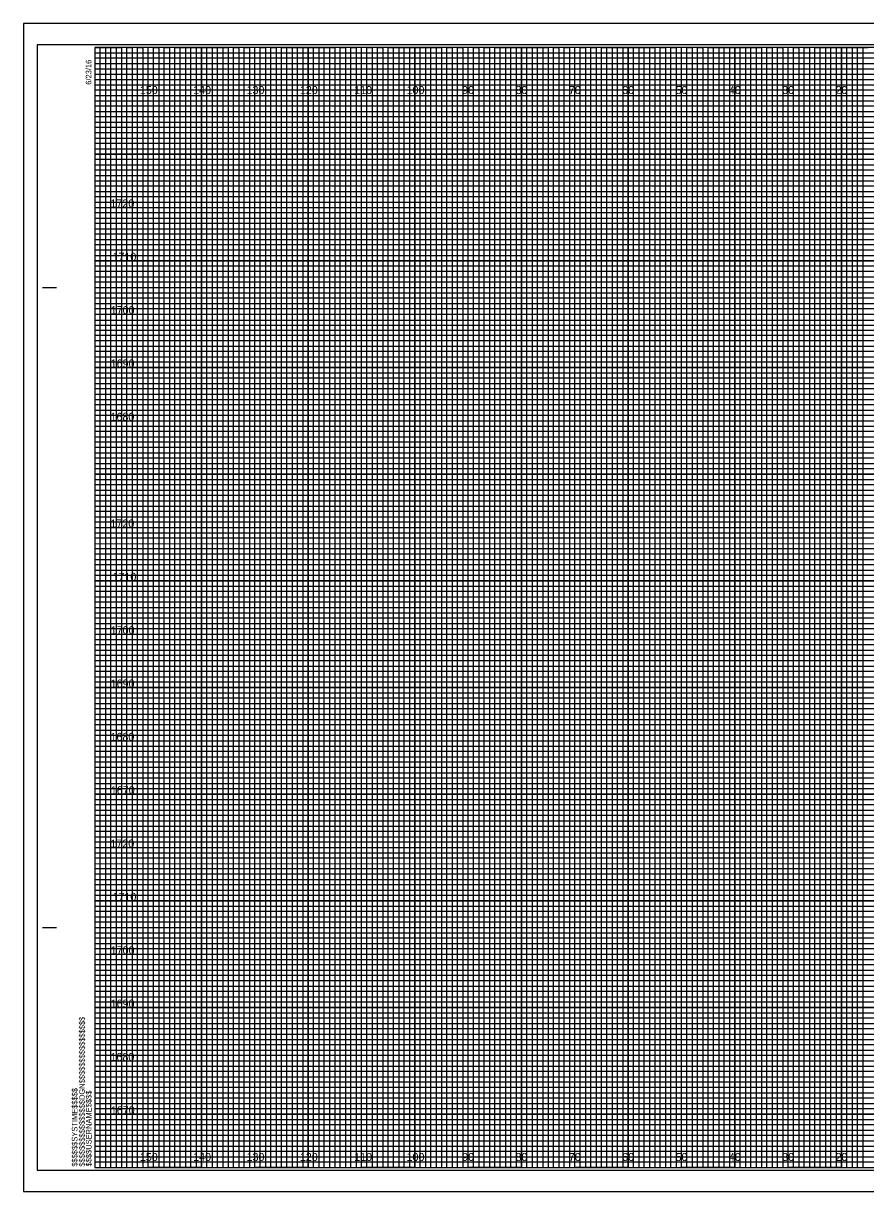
# Model space of a CAD drawing. Extents: x 656 to 993, y -2 to 2857.
# Drawn here: x 656.3 to 814.2, y 2198.3 to 2417.3 of the extents above; entities that cross this region are included whole.
import ezdxf

# ---------------------------------------------------------------- set-up
doc = ezdxf.new("R2010")
doc.units = 0
for name, color, linetype in [('Prop RDY Alternate Text Blue', 7, 'Continuous'), ('Prop Retaining Wall', 7, 'Continuous'), ('Prop SS Cut Line', 7, 'Continuous'), ('Prop SS Fill Line', 7, 'Continuous'), ('Prop SS Transition Line', 7, 'Continuous'), ('Raster_Level_0', 7, 'Continuous'), ('Raster_Level_3', 7, 'Continuous'), ('Scratch_Level_3', 7, 'Continuous'), ('Scratch_Level_7', 7, 'Continuous'), ('Typical Guardrail CELL', 7, 'Continuous'), ('Typical Text Asphalt at Bridge Approach CELL', 7, 'Continuous')]:
    doc.layers.add(name, color=color, linetype=linetype)

msp = doc.modelspace()

# ---------------------------------------------------------------- linework, layer by layer
at = {"layer": 'Prop RDY Alternate Text Blue'}
for p, q in [((679.74, 2202.8), (679.74, 2412.8)), ((689.74, 2202.8), (689.74, 2412.8)), ((699.74, 2202.8), (699.74, 2412.8)), ((709.74, 2202.8), (709.74, 2412.8)), ((719.74, 2202.8), (719.74, 2412.8)), ((729.74, 2202.8), (729.74, 2412.8)), ((739.74, 2202.8), (739.74, 2412.8)), ((749.74, 2202.8), (749.74, 2412.8)), ((759.74, 2202.8), (759.74, 2412.8)), ((769.74, 2202.8), (769.74, 2412.8)), ((779.74, 2202.8), (779.74, 2412.8)), ((789.74, 2202.8), (789.74, 2412.8)), ((799.74, 2202.8), (799.74, 2412.8)), ((809.74, 2202.8), (809.74, 2412.8)), ((669.74, 2402.8), (989.74, 2402.8)), ((669.74, 2392.8), (989.74, 2392.8)), ((669.74, 2382.8), (989.74, 2382.8)), ((669.74, 2372.8), (989.74, 2372.8)), ((669.74, 2362.8), (989.74, 2362.8)), ((669.74, 2352.8), (989.74, 2352.8)), ((669.74, 2342.8), (989.74, 2342.8)), ((669.74, 2332.8), (989.74, 2332.8)), ((669.74, 2322.8), (989.74, 2322.8)), ((669.74, 2312.8), (989.74, 2312.8)), ((669.74, 2302.8), (989.74, 2302.8)), ((669.74, 2292.8), (989.74, 2292.8)), ((669.74, 2282.8), (989.74, 2282.8)), ((669.74, 2272.8), (989.74, 2272.8)), ((669.74, 2262.8), (989.74, 2262.8)), ((669.74, 2252.8), (989.74, 2252.8)), ((669.74, 2242.8), (989.74, 2242.8)), ((669.74, 2232.8), (989.74, 2232.8)), ((669.74, 2222.8), (989.74, 2222.8)), ((669.74, 2212.8), (989.74, 2212.8))]:
    msp.add_line(p, q, dxfattribs=at)
at = {"layer": 'Prop Retaining Wall'}
for p, q in [((659.94, 2367.8), (662.44, 2367.8)), ((660.04, 2367.8), (662.54, 2367.8)), ((659.94, 2247.8), (662.44, 2247.8)), ((660.04, 2247.8), (662.54, 2247.8)), ((669.74, 2202.8), (669.74, 2202.8)), ((669.74, 2202.8), (669.74, 2202.8)), ((669.74, 2202.8), (669.74, 2202.8)), ((669.74, 2202.8), (669.74, 2202.8)), ((669.74, 2202.8), (669.74, 2202.8)), ((669.74, 2202.8), (669.74, 2202.8)), ((669.74, 2202.8), (669.74, 2202.8))]:
    msp.add_line(p, q, dxfattribs=at)
msp.add_lwpolyline([(989.74, 2412.8), (669.74, 2412.8), (669.74, 2202.8), (989.74, 2202.8)], close=True, dxfattribs=at)
at = {"layer": 'Prop SS Cut Line'}
for points in [[(669.74, 2412.8), (674.74, 2412.8), (674.74, 2202.8), (684.74, 2202.8), (684.74, 2412.8), (694.74, 2412.8), (694.74, 2202.8), (704.74, 2202.8), (704.74, 2412.8), (714.74, 2412.8), (714.74, 2202.8), (724.74, 2202.8), (724.74, 2412.8), (734.74, 2412.8), (734.74, 2202.8), (744.74, 2202.8), (744.74, 2412.8), (754.74, 2412.8), (754.74, 2202.8), (764.74, 2202.8), (764.74, 2412.8), (774.74, 2412.8), (774.74, 2202.8), (784.74, 2202.8), (784.74, 2412.8), (794.74, 2412.8), (794.74, 2202.8), (804.74, 2202.8), (804.74, 2412.8), (814.74, 2412.8)], [(669.74, 2407.8), (944.74, 2407.8)], [(669.74, 2387.8), (989.74, 2387.8), (989.74, 2397.8), (669.74, 2397.8)], [(669.74, 2367.8), (989.74, 2367.8), (989.74, 2377.8), (669.74, 2377.8)], [(669.74, 2347.8), (989.74, 2347.8), (989.74, 2357.8), (669.74, 2357.8)], [(669.74, 2327.8), (989.74, 2327.8), (989.74, 2337.8), (669.74, 2337.8)], [(669.74, 2307.8), (989.74, 2307.8), (989.74, 2317.8), (669.74, 2317.8)], [(669.74, 2287.8), (989.74, 2287.8), (989.74, 2297.8), (669.74, 2297.8)], [(669.74, 2267.8), (989.74, 2267.8), (989.74, 2277.8), (669.74, 2277.8)], [(669.74, 2247.8), (989.74, 2247.8), (989.74, 2257.8), (669.74, 2257.8)], [(669.74, 2227.8), (989.74, 2227.8), (989.74, 2237.8), (669.74, 2237.8)], [(669.74, 2207.8), (989.74, 2207.8), (989.74, 2217.8), (669.74, 2217.8)]]:
    msp.add_lwpolyline(points, dxfattribs=at)
at = {"layer": 'Prop SS Fill Line'}
for p, q in [((679.74, 2412.8), (669.74, 2412.8)), ((679.74, 2202.8), (679.74, 2412.8)), ((699.74, 2412.8), (689.74, 2412.8)), ((689.74, 2412.8), (689.74, 2202.8)), ((699.74, 2202.8), (699.74, 2412.8)), ((719.74, 2412.8), (709.74, 2412.8)), ((709.74, 2412.8), (709.74, 2202.8)), ((719.74, 2202.8), (719.74, 2412.8)), ((739.74, 2412.8), (729.74, 2412.8)), ((729.74, 2412.8), (729.74, 2202.8)), ((739.74, 2202.8), (739.74, 2412.8)), ((759.74, 2412.8), (749.74, 2412.8)), ((749.74, 2412.8), (749.74, 2202.8)), ((759.74, 2202.8), (759.74, 2412.8)), ((779.74, 2412.8), (769.74, 2412.8)), ((769.74, 2412.8), (769.74, 2202.8)), ((779.74, 2202.8), (779.74, 2412.8)), ((799.74, 2412.8), (789.74, 2412.8)), ((789.74, 2412.8), (789.74, 2202.8)), ((799.74, 2202.8), (799.74, 2412.8)), ((819.74, 2412.8), (809.74, 2412.8)), ((809.74, 2412.8), (809.74, 2202.8)), ((689.74, 2202.8), (679.74, 2202.8)), ((709.74, 2202.8), (699.74, 2202.8)), ((729.74, 2202.8), (719.74, 2202.8)), ((749.74, 2202.8), (739.74, 2202.8)), ((769.74, 2202.8), (759.74, 2202.8)), ((789.74, 2202.8), (779.74, 2202.8)), ((809.74, 2202.8), (799.74, 2202.8))]:
    msp.add_line(p, q, dxfattribs=at)
for points in [[(669.74, 2402.8), (989.74, 2402.8), (989.74, 2392.8), (669.74, 2392.8)], [(669.74, 2382.8), (989.74, 2382.8), (989.74, 2372.8), (669.74, 2372.8)], [(669.74, 2362.8), (989.74, 2362.8), (989.74, 2352.8), (669.74, 2352.8)], [(669.74, 2342.8), (989.74, 2342.8), (989.74, 2332.8), (669.74, 2332.8)], [(669.74, 2322.8), (989.74, 2322.8), (989.74, 2312.8), (669.74, 2312.8)], [(669.74, 2302.8), (989.74, 2302.8), (989.74, 2292.8), (669.74, 2292.8)], [(669.74, 2282.8), (989.74, 2282.8), (989.74, 2272.8), (669.74, 2272.8)], [(669.74, 2262.8), (989.74, 2262.8), (989.74, 2252.8), (669.74, 2252.8)], [(669.74, 2242.8), (989.74, 2242.8), (989.74, 2232.8), (669.74, 2232.8)], [(669.74, 2222.8), (989.74, 2222.8), (989.74, 2212.8), (669.74, 2212.8)]]:
    msp.add_lwpolyline(points, dxfattribs=at)
at = {"layer": 'Prop SS Transition Line'}
for p, q in [((669.74, 2411.8), (929.74, 2411.8)), ((929.74, 2410.78), (669.74, 2410.78)), ((669.74, 2410.78), (669.74, 2409.8)), ((669.74, 2409.8), (929.74, 2409.8)), ((929.74, 2408.69), (669.74, 2408.69)), ((669.74, 2408.69), (669.74, 2406.8)), ((669.74, 2406.8), (989.74, 2406.8))]:
    msp.add_line(p, q, dxfattribs=at)
for points in [[(669.74, 2405.8), (939.74, 2405.8), (989.74, 2405.8), (989.74, 2404.8), (669.74, 2404.8)], [(669.74, 2403.8), (989.74, 2403.8), (989.74, 2401.8), (669.74, 2401.8)], [(669.74, 2400.8), (989.74, 2400.8), (989.74, 2399.8), (669.74, 2399.78)], [(669.74, 2398.8), (989.74, 2398.8), (989.74, 2396.8), (669.74, 2396.8)], [(669.74, 2395.8), (989.74, 2395.8), (989.74, 2394.8), (669.74, 2394.8)], [(669.74, 2393.8), (989.74, 2393.8), (989.74, 2391.8), (669.74, 2391.8)], [(669.74, 2390.8), (989.74, 2390.8), (989.74, 2389.8), (669.74, 2389.8)], [(669.74, 2388.8), (989.74, 2388.8), (989.74, 2386.8), (669.74, 2386.8)], [(669.74, 2385.8), (989.74, 2385.8), (989.74, 2384.8), (669.74, 2384.8)], [(669.74, 2383.8), (989.74, 2383.8), (989.74, 2381.8), (669.74, 2381.8)], [(669.74, 2380.8), (989.74, 2380.8), (989.74, 2379.8), (669.74, 2379.8)], [(669.74, 2378.8), (989.74, 2378.8), (989.74, 2376.75), (989.74, 2375.8), (989.74, 2374.8), (669.74, 2374.8)], [(669.74, 2376.8), (989.74, 2376.8), (989.74, 2375.8), (669.74, 2375.8)], [(669.74, 2373.8), (989.74, 2373.8), (989.74, 2371.8), (669.74, 2371.83)], [(669.74, 2371.83), (989.74, 2371.8), (989.74, 2370.8), (669.74, 2370.8)], [(669.74, 2369.8), (989.74, 2369.8), (989.74, 2368.8), (669.74, 2368.8)], [(669.74, 2366.8), (989.74, 2366.8), (989.74, 2365.8), (669.74, 2365.8)], [(669.74, 2364.8), (989.74, 2364.8), (989.74, 2363.8), (669.74, 2363.8)], [(669.67, 2361.69), (989.74, 2361.69), (989.74, 2360.68), (669.67, 2360.68)], [(669.74, 2359.8), (989.74, 2359.8), (989.74, 2358.8), (669.74, 2358.8)], [(669.74, 2356.8), (989.74, 2356.8), (989.74, 2355.8), (669.74, 2355.8)], [(669.74, 2354.8), (989.74, 2354.8), (989.74, 2353.8), (669.74, 2353.8)], [(669.74, 2351.8), (989.74, 2351.8), (989.74, 2350.8), (669.74, 2350.8)], [(669.74, 2349.8), (989.74, 2349.8), (989.74, 2348.8), (669.74, 2348.8)], [(669.74, 2346.8), (989.74, 2346.8), (989.74, 2345.8), (669.74, 2345.8)], [(669.74, 2344.8), (989.74, 2344.8), (989.74, 2343.8), (669.74, 2343.8)], [(669.74, 2341.8), (989.74, 2341.8), (989.73, 2340.78), (669.74, 2340.8)], [(669.74, 2339.8), (989.74, 2339.8), (989.74, 2338.8), (669.74, 2338.8)], [(669.74, 2336.8), (989.74, 2336.8), (989.74, 2335.8), (669.74, 2335.8)], [(669.74, 2334.8), (989.74, 2334.8), (989.74, 2333.8), (669.74, 2333.8)], [(669.74, 2331.8), (989.74, 2331.8), (989.74, 2330.8), (669.74, 2330.8)], [(669.74, 2329.8), (989.74, 2329.8), (989.74, 2328.8), (669.74, 2328.8)], [(669.74, 2326.8), (989.74, 2326.8), (989.74, 2325.8), (669.74, 2325.8)], [(669.74, 2324.8), (989.74, 2324.8), (989.74, 2323.8), (669.74, 2323.8)], [(669.74, 2321.8), (989.74, 2321.8), (989.74, 2320.8), (669.74, 2320.8)], [(669.74, 2319.79), (989.81, 2319.71), (989.74, 2318.8), (669.74, 2318.8)], [(669.74, 2316.8), (989.74, 2316.8), (989.74, 2315.8), (669.74, 2315.8)], [(669.74, 2314.8), (989.74, 2314.8), (989.74, 2313.8), (669.74, 2313.8)], [(669.74, 2311.8), (989.74, 2311.8), (989.74, 2310.8), (669.74, 2310.8)], [(669.74, 2309.8), (989.74, 2309.8), (989.74, 2308.8), (669.74, 2308.8)], [(669.74, 2306.8), (989.74, 2306.8), (989.74, 2305.8), (669.74, 2305.8)], [(669.74, 2304.8), (989.74, 2304.8), (989.74, 2303.8), (669.74, 2303.8)], [(669.74, 2301.8), (989.74, 2301.8), (989.74, 2300.8), (669.74, 2300.8)], [(669.74, 2299.8), (989.74, 2299.8), (989.74, 2298.8), (669.74, 2298.8)], [(669.74, 2296.8), (989.74, 2296.8), (989.74, 2295.8), (669.74, 2295.8)], [(669.74, 2294.8), (989.74, 2294.8), (989.74, 2293.8), (669.74, 2293.8)], [(669.74, 2291.8), (989.74, 2291.8), (989.74, 2290.8), (669.74, 2290.8)], [(669.74, 2289.8), (989.74, 2289.8), (989.74, 2288.8), (669.74, 2288.8)], [(669.74, 2286.8), (989.74, 2286.8), (989.74, 2285.8), (669.74, 2285.8)], [(669.74, 2284.8), (989.74, 2284.8), (989.74, 2283.8), (669.74, 2283.8)], [(669.74, 2281.8), (989.74, 2281.8), (989.73, 2280.78), (669.74, 2280.8)], [(669.74, 2279.8), (989.74, 2279.8), (989.74, 2278.8), (669.74, 2278.8)], [(669.74, 2276.8), (989.74, 2276.8), (989.74, 2275.8), (669.74, 2275.8)], [(669.74, 2274.8), (989.74, 2274.8), (989.74, 2273.8), (669.74, 2273.8)], [(669.74, 2271.8), (989.74, 2271.8), (989.74, 2270.8), (669.74, 2270.8)], [(669.74, 2269.8), (989.74, 2269.8), (989.74, 2268.8), (669.74, 2268.8)], [(669.74, 2266.8), (989.74, 2266.8), (989.74, 2265.8), (669.74, 2265.8)], [(669.74, 2264.8), (989.74, 2264.8), (989.74, 2263.8), (669.74, 2263.8)], [(669.74, 2261.8), (989.74, 2261.8), (989.74, 2260.8), (669.74, 2260.8)], [(669.74, 2259.79), (989.81, 2259.71), (989.74, 2258.8), (669.74, 2258.8)], [(669.74, 2256.8), (989.74, 2256.8), (989.74, 2255.8), (669.74, 2255.8)], [(669.74, 2254.8), (989.74, 2254.8), (989.74, 2253.8), (669.74, 2253.8)], [(669.74, 2251.8), (989.74, 2251.8), (989.74, 2250.8), (669.74, 2250.8)], [(669.74, 2249.8), (989.74, 2249.8), (989.74, 2248.8), (669.74, 2248.8)], [(669.74, 2246.8), (989.74, 2246.8), (989.74, 2245.8), (669.74, 2245.8)], [(669.74, 2244.8), (989.74, 2244.8), (989.74, 2243.8), (669.74, 2243.8)], [(669.74, 2241.8), (989.74, 2241.8), (989.74, 2240.8), (669.74, 2240.8)], [(669.74, 2239.8), (989.74, 2239.8), (989.74, 2238.8), (669.74, 2238.8)], [(669.74, 2236.8), (989.74, 2236.8), (989.74, 2235.8), (669.74, 2235.8)], [(669.74, 2234.8), (989.74, 2234.8), (989.74, 2233.8), (669.74, 2233.8)], [(669.74, 2231.8), (989.74, 2231.8), (989.74, 2230.8), (669.74, 2230.8)], [(669.74, 2229.8), (989.74, 2229.8), (989.74, 2228.8), (669.74, 2228.8)], [(669.74, 2226.8), (989.74, 2226.8), (989.74, 2225.8), (669.74, 2225.8)], [(669.74, 2224.8), (989.74, 2224.8), (989.74, 2223.8), (669.74, 2223.8)], [(669.74, 2221.8), (989.74, 2221.8), (989.74, 2220.8), (669.74, 2220.8)], [(669.74, 2219.8), (989.74, 2219.8), (989.74, 2218.8), (669.74, 2218.8)], [(669.74, 2216.8), (989.74, 2216.8), (989.74, 2215.8), (669.74, 2215.8)], [(669.74, 2214.8), (989.74, 2214.8), (989.74, 2213.8), (669.74, 2213.8)], [(669.74, 2211.8), (989.74, 2211.8), (989.74, 2210.8), (669.74, 2210.8)], [(669.74, 2209.8), (989.74, 2209.8), (989.74, 2208.8), (669.74, 2208.8)], [(669.74, 2206.8), (989.74, 2206.8), (989.74, 2205.8), (669.74, 2205.8)], [(669.74, 2204.8), (989.74, 2204.8), (989.74, 2203.8), (669.74, 2203.8)]]:
    msp.add_lwpolyline(points, dxfattribs=at)
at = {"layer": 'Raster_Level_3'}
for points in [[(669.74, 2202.8), (670.74, 2202.8), (670.74, 2412.8), (671.74, 2412.8), (671.74, 2202.8)], [(671.74, 2202.8), (672.74, 2202.8), (672.74, 2412.8), (673.74, 2412.8), (673.74, 2202.8)], [(674.74, 2202.8), (675.74, 2202.8), (675.74, 2412.8), (676.74, 2412.8), (676.74, 2202.8)], [(676.74, 2202.8), (677.74, 2202.8), (677.74, 2412.8), (678.74, 2412.8), (678.74, 2202.8)], [(679.74, 2202.8), (680.74, 2202.8), (680.74, 2412.8), (681.74, 2412.8), (681.74, 2202.8)], [(681.74, 2202.8), (682.74, 2202.8), (682.74, 2412.8), (683.74, 2412.8), (683.74, 2202.8)], [(684.74, 2202.8), (685.74, 2202.8), (685.74, 2412.8), (686.74, 2412.8), (686.74, 2202.8)], [(686.74, 2202.8), (687.74, 2202.8), (687.74, 2412.8), (688.74, 2412.8), (688.74, 2202.8)], [(689.74, 2202.8), (690.74, 2202.8), (690.74, 2412.8), (691.74, 2412.8), (691.74, 2202.8)], [(691.74, 2202.8), (692.74, 2202.8), (692.74, 2412.8), (693.74, 2412.8), (693.74, 2202.8)], [(694.74, 2202.8), (695.74, 2202.8), (695.74, 2412.8), (696.74, 2412.8), (696.74, 2202.8)], [(696.74, 2202.8), (697.74, 2202.8), (697.74, 2412.8), (698.74, 2412.8), (698.74, 2202.8)], [(699.74, 2202.8), (700.74, 2202.8), (700.74, 2412.8), (701.74, 2412.8), (701.74, 2202.8)], [(701.74, 2202.8), (702.74, 2202.8), (702.74, 2412.8), (703.74, 2412.8), (703.74, 2202.8)], [(704.74, 2202.8), (705.74, 2202.8), (705.74, 2412.8), (706.74, 2412.8), (706.74, 2202.8)], [(706.74, 2202.8), (707.74, 2202.8), (707.74, 2412.8), (708.74, 2412.8), (708.74, 2202.8)], [(709.74, 2202.8), (710.74, 2202.8), (710.74, 2412.8), (711.74, 2412.8), (711.74, 2202.8)], [(711.74, 2202.8), (712.74, 2202.8), (712.74, 2412.8), (713.74, 2412.8), (713.74, 2202.8)], [(714.74, 2202.8), (715.74, 2202.8), (715.74, 2412.8), (716.74, 2412.8), (716.74, 2202.8)], [(716.74, 2202.8), (717.74, 2202.8), (717.74, 2412.8), (718.74, 2412.8), (718.74, 2202.8)], [(719.74, 2202.8), (720.74, 2202.8), (720.74, 2412.8), (721.74, 2412.8), (721.74, 2202.8)], [(721.74, 2202.8), (722.74, 2202.8), (722.74, 2412.8), (723.74, 2412.8), (723.74, 2202.8)], [(724.74, 2202.8), (725.74, 2202.8), (725.74, 2412.8), (726.74, 2412.8), (726.74, 2202.8)], [(726.74, 2202.8), (727.74, 2202.8), (727.74, 2412.8), (728.74, 2412.8), (728.74, 2202.8)], [(729.74, 2202.8), (730.74, 2202.8), (730.74, 2412.8), (731.74, 2412.8), (731.74, 2202.8)], [(731.74, 2202.8), (732.74, 2202.8), (732.74, 2412.8), (733.74, 2412.8), (733.74, 2202.8)], [(734.74, 2202.8), (735.74, 2202.8), (735.74, 2412.8), (736.74, 2412.8), (736.74, 2202.8)], [(736.74, 2202.8), (737.74, 2202.8), (737.74, 2412.8), (738.74, 2412.8), (738.74, 2202.8)], [(739.74, 2202.8), (740.74, 2202.8), (740.74, 2412.8), (741.74, 2412.8), (741.74, 2202.8)], [(741.74, 2202.8), (742.74, 2202.8), (742.74, 2412.8), (743.74, 2412.8), (743.74, 2202.8)], [(744.74, 2202.8), (745.74, 2202.8), (745.74, 2412.8), (746.74, 2412.8), (746.74, 2202.8)], [(746.74, 2202.8), (747.74, 2202.8), (747.74, 2412.8), (748.74, 2412.8), (748.74, 2202.8)], [(749.74, 2202.8), (750.74, 2202.8), (750.74, 2412.8), (751.74, 2412.8), (751.74, 2202.8)], [(751.74, 2202.8), (752.74, 2202.8), (752.74, 2412.8), (753.74, 2412.8), (753.74, 2202.8)], [(754.74, 2202.8), (755.74, 2202.8), (755.74, 2412.8), (756.74, 2412.8), (756.74, 2202.8)], [(756.74, 2202.8), (757.74, 2202.8), (757.74, 2412.8), (758.74, 2412.8), (758.74, 2202.8)], [(759.74, 2202.8), (760.74, 2202.8), (760.74, 2412.8), (761.74, 2412.8), (761.74, 2202.8)], [(761.74, 2202.8), (762.74, 2202.8), (762.74, 2412.8), (763.74, 2412.8), (763.74, 2202.8)], [(764.74, 2202.8), (765.74, 2202.8), (765.74, 2412.8), (766.74, 2412.8), (766.74, 2202.8)], [(766.74, 2202.8), (767.74, 2202.8), (767.74, 2412.8), (768.74, 2412.8), (768.74, 2202.8)], [(769.74, 2202.8), (770.74, 2202.8), (770.74, 2412.8), (771.74, 2412.8), (771.74, 2202.8)], [(771.74, 2202.8), (772.74, 2202.8), (772.74, 2412.8), (773.74, 2412.8), (773.74, 2202.8)], [(774.74, 2202.8), (775.74, 2202.8), (775.74, 2412.8), (776.74, 2412.8), (776.74, 2202.8)], [(776.74, 2202.8), (777.74, 2202.8), (777.74, 2412.8), (778.74, 2412.8), (778.74, 2202.8)], [(779.74, 2202.8), (780.74, 2202.8), (780.74, 2412.8), (781.74, 2412.8), (781.74, 2202.8)], [(781.74, 2202.8), (782.74, 2202.8), (782.74, 2412.8), (783.74, 2412.8), (783.74, 2202.8)], [(784.74, 2202.8), (785.74, 2202.8), (785.74, 2412.8), (786.74, 2412.8), (786.74, 2202.8)], [(786.74, 2202.8), (787.74, 2202.8), (787.74, 2412.8), (788.74, 2412.8), (788.74, 2202.8)], [(789.74, 2202.8), (790.74, 2202.8), (790.74, 2412.8), (791.74, 2412.8), (791.74, 2202.8)], [(791.74, 2202.8), (792.74, 2202.8), (792.74, 2412.8), (793.74, 2412.8), (793.74, 2202.8)], [(794.74, 2202.8), (795.74, 2202.8), (795.74, 2412.8), (796.74, 2412.8), (796.74, 2202.8)], [(796.74, 2202.8), (797.74, 2202.8), (797.74, 2412.8), (798.74, 2412.8), (798.74, 2202.8)], [(799.74, 2202.8), (800.74, 2202.8), (800.74, 2412.8), (801.74, 2412.8), (801.74, 2202.8)], [(801.74, 2202.8), (802.74, 2202.8), (802.74, 2412.8), (803.74, 2412.8), (803.74, 2202.8)], [(804.74, 2202.8), (805.74, 2202.8), (805.74, 2412.8), (806.74, 2412.8), (806.74, 2202.8)], [(806.74, 2202.8), (807.74, 2202.8), (807.74, 2412.8), (808.74, 2412.8), (808.74, 2202.8)], [(809.74, 2202.8), (810.74, 2202.8), (810.74, 2412.8), (811.74, 2412.8), (811.74, 2202.8)], [(811.74, 2202.8), (812.74, 2202.8), (812.74, 2412.8), (813.74, 2412.8), (813.74, 2202.8)]]:
    msp.add_lwpolyline(points, dxfattribs=at)
at = {"layer": 'Scratch_Level_7'}
msp.add_lwpolyline([(656.34, 2198.3), (993.04, 2198.3), (993.04, 2417.3), (656.34, 2417.3)], close=True, dxfattribs=at)
at = {"layer": 'Typical Guardrail CELL'}
msp.add_lwpolyline([(658.94, 2202.3), (992.14, 2202.3), (992.14, 2413.3), (658.94, 2413.3)], close=True, dxfattribs=at)
at = {"layer": 'Typical Text Asphalt at Bridge Approach CELL'}
for p, q in [((993.04, 2417.3), (656.34, 2417.3)), ((656.34, 2417.3), (656.34, 2198.3)), ((656.34, 2198.3), (993.04, 2198.3))]:
    msp.add_line(p, q, dxfattribs=at)

# ---------------------------------------------------------------- texts
at = {"layer": 'Prop Retaining Wall'}
for s, p in [('6/23/16', (669.09, 2405.8)), ('$$$$$$$$$$$$$$$$DGN$$$$$$$$$$$$$$$$', (667.86, 2202.98)), ('$$$$$$SYSTIME$$$$$', (666.48, 2202.98)), ('$$$$USERNAME$$$$', (669.12, 2203.03))]:
    msp.add_text(s, height=1.05, rotation=90, dxfattribs=at).set_placement(p)
at = {"layer": 'Raster_Level_0'}
for s, p in [('150', (678.18, 2404.05)), ('140', (688.18, 2404.05)), ('130', (698.18, 2404.05)), ('120', (708.18, 2404.05)), ('110', (718.36, 2404.05)), ('100', (728.18, 2404.05)), ('90', (738.6, 2404.05)), ('80', (748.6, 2404.05)), ('70', (758.6, 2404.05)), ('60', (768.6, 2404.05)), ('50', (778.6, 2404.05)), ('40', (788.6, 2404.05)), ('30', (798.6, 2404.05)), ('20', (808.6, 2404.05)), ('150', (678.18, 2204.05)), ('140', (688.18, 2204.05)), ('130', (698.18, 2204.05)), ('120', (708.18, 2204.05)), ('110', (718.36, 2204.05)), ('100', (728.18, 2204.05)), ('90', (738.6, 2204.05)), ('80', (748.6, 2204.05)), ('70', (758.6, 2204.05)), ('60', (768.6, 2204.05)), ('50', (778.6, 2204.05)), ('40', (788.6, 2204.05)), ('30', (798.6, 2204.05)), ('20', (808.6, 2204.05))]:
    msp.add_text(s, height=1.5, dxfattribs=at).set_placement(p)
at = {"layer": 'Scratch_Level_3'}
for s, p in [('1720', (672.67, 2382.8)), ('1710', (673.05, 2372.8)), ('1700', (672.72, 2362.8)), ('1690', (672.71, 2352.8)), ('1680', (672.68, 2342.8)), ('1720', (672.67, 2322.8)), ('1710', (673.05, 2312.8)), ('1700', (672.72, 2302.8)), ('1690', (672.71, 2292.8)), ('1680', (672.68, 2282.8)), ('1670', (672.74, 2272.8)), ('1720', (672.67, 2262.8)), ('1710', (673.05, 2252.8)), ('1700', (672.72, 2242.8)), ('1690', (672.71, 2232.8)), ('1680', (672.68, 2222.8)), ('1670', (672.74, 2212.8))]:
    msp.add_text(s, height=1.5, dxfattribs=at).set_placement(p)

doc.saveas('drawing.dxf')
